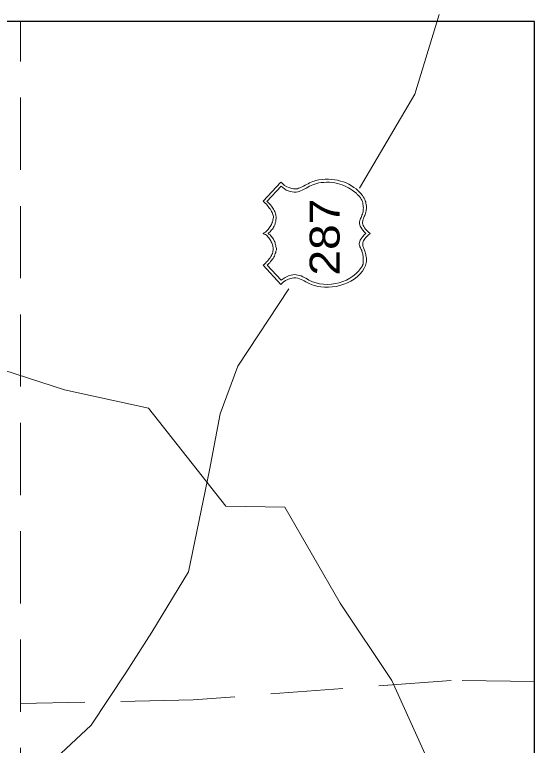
# Model space of a CAD drawing. Extents: x 2363323 to 2367082, y 6956018 to 6980837.
# Drawn here: x 2366145.8 to 2366234.3, y 6956959.3 to 6957083.7 of the extents above; entities that cross this region are included whole.
import ezdxf

# ---------------------------------------------------------------- set-up
doc = ezdxf.new("R2010")
doc.units = 0
doc.header["$LTSCALE"] = 4.1
doc.linetypes.add('MEDIUM_DASHED', pattern=[4.5, 3, -1.5])
doc.layers.add('62', color=7, linetype='Continuous', lineweight=13)
doc.layers.add('63', color=7, linetype='Continuous', lineweight=13)

msp = doc.modelspace()

# ---------------------------------------------------------------- linework, layer by layer
at = {"layer": '62'}
for p, q in [((2366218.108, 6957083.742), (2366213.919, 6957070.216)), ((2366213.919, 6957070.216), (2366204.537, 6957054.172)), ((2366183.835, 6957023.884), (2366192.476, 6957037.071))]:
    msp.add_line(p, q, dxfattribs=at)
at = {"layer": '62', "linetype": 'MEDIUM_DASHED'}
msp.add_line((2366146.841, 6956632.956), (2366146.84, 6957082.55), dxfattribs=at)
at = {"layer": '62', "lineweight": 25}
msp.add_lwpolyline([(2365769.011, 6956632.956), (2366234.284, 6956632.956), (2366234.284, 6957082.548), (2365769.009, 6957082.548)], dxfattribs=at)
at = {"layer": '62'}
for points in [[(2366191.149, 6957037.815), (2366188.156, 6957041.076), (2366188.336, 6957041.258), (2366188.539, 6957041.436), (2366188.696, 6957041.638), (2366188.877, 6957041.796), (2366189.033, 6957042.002), (2366189.17, 6957042.18), (2366189.303, 6957042.36), (2366189.439, 6957042.562), (2366189.53, 6957042.72), (2366189.619, 6957042.922), (2366189.71, 6957043.102), (2366189.755, 6957043.305), (2366189.8, 6957043.485), (2366189.842, 6957043.642), (2366189.845, 6957043.868), (2366189.845, 6957044.07), (2366189.799, 6957044.205), (2366189.753, 6957044.362), (2366189.731, 6957044.542), (2366189.663, 6957044.721), (2366189.596, 6957044.904), (2366189.506, 6957045.06), (2366189.439, 6957045.242), (2366189.35, 6957045.42), (2366189.215, 6957045.578), (2366189.08, 6957045.758), (2366188.945, 6957045.915), (2366188.833, 6957046.072), (2366188.673, 6957046.185), (2366188.517, 6957046.32), (2366188.315, 6957046.388), (2366188.157, 6957046.5), (2366188.313, 6957046.612), (2366188.516, 6957046.725), (2366188.696, 6957046.86), (2366188.833, 6957046.995), (2366188.99, 6957047.154), (2366189.125, 6957047.332), (2366189.236, 6957047.49), (2366189.35, 6957047.67), (2366189.461, 6957047.848), (2366189.573, 6957048.008), (2366189.62, 6957048.232), (2366189.709, 6957048.392), (2366189.755, 6957048.638), (2366189.799, 6957048.795), (2366189.845, 6957049.02), (2366189.867, 6957049.202), (2366189.866, 6957049.358), (2366189.843, 6957049.56), (2366189.777, 6957049.695), (2366189.733, 6957049.896), (2366189.663, 6957050.078), (2366189.573, 6957050.236), (2366189.485, 6957050.394), (2366189.371, 6957050.595), (2366189.236, 6957050.754), (2366189.125, 6957050.932), (2366188.966, 6957051.09), (2366188.831, 6957051.292), (2366188.675, 6957051.452), (2366188.493, 6957051.63), (2366188.313, 6957051.788), (2366188.156, 6957051.968), (2366191.149, 6957055.232), (2366191.465, 6957054.938), (2366191.779, 6957054.646), (2366192.161, 6957054.442), (2366192.566, 6957054.286), (2366192.95, 6957054.128), (2366193.287, 6957054.058), (2366193.579, 6957054.06), (2366193.781, 6957054.06), (2366193.963, 6957054.105), (2366194.163, 6957054.174), (2366194.345, 6957054.24), (2366194.569, 6957054.33), (2366194.793, 6957054.442), (2366195.019, 6957054.555), (2366195.266, 6957054.692), (2366195.513, 6957054.825), (2366195.785, 6957054.96), (2366196.031, 6957055.095), (2366196.325, 6957055.208), (2366196.573, 6957055.32), (2366196.82, 6957055.41), (2366197.066, 6957055.5), (2366197.337, 6957055.568), (2366197.583, 6957055.612), (2366198.147, 6957055.68), (2366198.71, 6957055.749), (2366199.227, 6957055.748), (2366199.766, 6957055.68), (2366200.306, 6957055.636), (2366200.803, 6957055.545), (2366201.297, 6957055.41), (2366201.791, 6957055.252), (2366202.263, 6957055.095), (2366202.737, 6957054.87)], [(2366203.501, 6957053.678), (2366203.277, 6957053.88), (2366202.961, 6957054.062), (2366202.647, 6957054.24), (2366202.309, 6957054.42), (2366201.95, 6957054.578), (2366201.567, 6957054.736), (2366201.185, 6957054.872), (2366200.756, 6957054.982), (2366200.307, 6957055.095), (2366199.879, 6957055.14), (2366199.407, 6957055.206), (2366198.933, 6957055.209), (2366198.44, 6957055.185), (2366198.011, 6957055.14), (2366197.607, 6957055.095), (2366197.27, 6957054.984), (2366196.91, 6957054.892), (2366196.593, 6957054.758), (2366196.301, 6957054.645), (2366196.009, 6957054.51), (2366195.74, 6957054.352), (2366195.469, 6957054.196), (2366195.243, 6957054.06), (2366194.996, 6957053.948), (2366194.749, 6957053.835), (2366194.48, 6957053.722), (2366194.255, 6957053.655), (2366194.006, 6957053.588), (2366193.736, 6957053.542), (2366193.421, 6957053.52), (2366193.083, 6957053.588), (2366192.746, 6957053.655), (2366192.409, 6957053.745), (2366192.05, 6957053.88), (2366191.756, 6957054.06), (2366191.463, 6957054.286), (2366191.171, 6957054.51), (2366188.763, 6957051.945), (2366188.921, 6957051.789), (2366189.08, 6957051.652), (2366189.259, 6957051.495), (2366189.395, 6957051.338), (2366189.551, 6957051.159), (2366189.663, 6957050.978), (2366189.776, 6957050.799), (2366189.889, 6957050.618), (2366190.001, 6957050.415), (2366190.113, 6957050.235), (2366190.181, 6957050.032), (2366190.226, 6957049.854), (2366190.295, 6957049.672), (2366190.316, 6957049.515), (2366190.339, 6957049.359), (2366190.363, 6957049.2), (2366190.339, 6957049.044), (2366190.316, 6957048.862), (2366190.317, 6957048.662), (2366190.271, 6957048.502), (2366190.203, 6957048.278), (2366190.159, 6957048.12), (2366190.091, 6957047.94), (2366190.003, 6957047.738), (2366189.911, 6957047.58), (2366189.821, 6957047.378), (2366189.71, 6957047.244), (2366189.573, 6957047.085), (2366189.461, 6957046.906), (2366189.303, 6957046.772), (2366189.147, 6957046.636), (2366188.966, 6957046.502), (2366189.123, 6957046.365), (2366189.303, 6957046.232), (2366189.416, 6957046.095), (2366189.551, 6957045.96), (2366189.641, 6957045.804), (2366189.753, 6957045.69), (2366189.867, 6957045.51), (2366189.956, 6957045.375), (2366190.025, 6957045.218), (2366190.115, 6957045.038), (2366190.16, 6957044.902), (2366190.203, 6957044.724), (2366190.249, 6957044.565), (2366190.317, 6957044.408), (2366190.316, 6957044.228), (2366190.361, 6957044.072), (2366190.385, 6957043.912), (2366190.383, 6957043.688), (2366190.316, 6957043.485), (2366190.293, 6957043.26), (2366190.203, 6957043.08), (2366190.137, 6957042.854), (2366190.046, 6957042.632), (2366189.933, 6957042.472), (2366189.821, 6957042.248), (2366189.686, 6957042.045), (2366189.573, 6957041.865), (2366189.392, 6957041.706), (2366189.259, 6957041.505), (2366189.079, 6957041.346)], [(2366202.737, 6957054.87), (2366203.163, 6957054.622), (2366203.546, 6957054.33), (2366203.975, 6957054.06), (2366204.333, 6957053.676), (2366204.695, 6957053.34), (2366205.01, 6957052.935), (2366205.167, 6957052.71), (2366205.301, 6957052.509), (2366205.413, 6957052.282), (2366205.503, 6957052.058), (2366205.595, 6957051.855), (2366205.616, 6957051.63), (2366205.663, 6957051.382), (2366205.706, 6957051.182), (2366205.706, 6957050.932), (2366205.706, 6957050.706), (2366205.683, 6957050.505), (2366205.661, 6957050.325), (2366205.593, 6957050.102), (2366205.549, 6957049.92), (2366205.505, 6957049.74), (2366205.413, 6957049.56), (2366205.346, 6957049.382), (2366205.28, 6957049.2), (2366205.211, 6957049.065), (2366205.145, 6957048.885), (2366205.121, 6957048.75), (2366205.076, 6957048.57), (2366205.031, 6957048.392), (2366205.055, 6957048.232), (2366205.1, 6957048.052), (2366205.166, 6957047.85), (2366205.279, 6957047.67), (2366205.391, 6957047.468), (2366205.549, 6957047.242), (2366205.751, 6957047.018), (2366206.021, 6957046.77), (2366206.313, 6957046.5), (2366206.043, 6957046.228), (2366205.819, 6957046.005), (2366205.593, 6957045.802), (2366205.436, 6957045.578), (2366205.303, 6957045.42), (2366205.213, 6957045.24), (2366205.143, 6957045.082), (2366205.1, 6957044.925), (2366205.076, 6957044.79), (2366205.077, 6957044.632), (2366205.077, 6957044.498), (2366205.121, 6957044.342), (2366205.166, 6957044.229), (2366205.189, 6957044.07), (2366205.279, 6957043.914), (2366205.323, 6957043.778), (2366205.391, 6957043.644), (2366205.437, 6957043.485), (2366205.503, 6957043.305), (2366205.549, 6957043.102), (2366205.593, 6957042.922), (2366205.616, 6957042.72), (2366205.663, 6957042.518), (2366205.707, 6957042.339), (2366205.706, 6957042.114), (2366205.706, 6957041.91), (2366205.707, 6957041.706), (2366205.663, 6957041.46), (2366205.617, 6957041.256), (2366205.549, 6957041.031), (2366205.459, 6957040.808), (2366205.346, 6957040.581), (2366205.009, 6957040.064), (2366204.581, 6957039.567), (2366204.131, 6957039.096), (2366203.613, 6957038.714), (2366203.053, 6957038.354), (2366202.466, 6957038.062), (2366201.859, 6957037.838), (2366201.206, 6957037.634), (2366200.555, 6957037.476), (2366199.901, 6957037.386), (2366199.226, 6957037.341), (2366198.573, 6957037.34), (2366197.919, 6957037.408), (2366197.293, 6957037.521), (2366196.661, 6957037.701), (2366196.099, 6957037.926), (2366195.873, 6957038.016), (2366195.626, 6957038.128), (2366195.401, 6957038.264), (2366195.133, 6957038.398), (2366194.863, 6957038.535), (2366194.593, 6957038.668), (2366194.321, 6957038.782), (2366194.03, 6957038.848), (2366193.715, 6957038.916), (2366193.376, 6957038.918), (2366193.04, 6957038.894), (2366192.701, 6957038.804), (2366192.319, 6957038.67), (2366191.937, 6957038.466)], [(2366188.809, 6957041.078), (2366191.171, 6957038.511), (2366191.533, 6957038.781), (2366191.893, 6957039.006), (2366192.229, 6957039.164), (2366192.543, 6957039.321), (2366192.881, 6957039.388), (2366193.173, 6957039.456), (2366193.443, 6957039.478), (2366193.759, 6957039.458), (2366194.053, 6957039.39), (2366194.321, 6957039.344), (2366194.593, 6957039.254), (2366194.863, 6957039.118), (2366195.131, 6957039.008), (2366195.401, 6957038.871), (2366195.65, 6957038.715), (2366195.919, 6957038.556), (2366196.503, 6957038.264), (2366197.135, 6957038.062), (2366197.741, 6957037.904), (2366198.416, 6957037.836), (2366199.069, 6957037.814), (2366199.743, 6957037.836), (2366200.419, 6957037.948), (2366201.049, 6957038.084), (2366201.679, 6957038.286), (2366202.309, 6957038.556), (2366202.873, 6957038.871), (2366203.413, 6957039.21), (2366203.883, 6957039.614), (2366204.333, 6957040.041), (2366204.695, 6957040.514), (2366205.009, 6957040.986), (2366205.053, 6957041.098), (2366205.123, 6957041.234), (2366205.143, 6957041.391), (2366205.143, 6957041.571), (2366205.166, 6957041.706), (2366205.167, 6957041.888), (2366205.167, 6957042.068), (2366205.167, 6957042.248), (2366205.145, 6957042.45), (2366205.143, 6957042.608), (2366205.1, 6957042.808), (2366205.076, 6957042.99), (2366205.033, 6957043.148), (2366204.987, 6957043.328), (2366204.919, 6957043.485), (2366204.896, 6957043.62), (2366204.807, 6957043.755), (2366204.737, 6957043.912), (2366204.673, 6957044.025), (2366204.603, 6957044.181), (2366204.559, 6957044.34), (2366204.537, 6957044.475), (2366204.493, 6957044.632), (2366204.491, 6957044.79), (2366204.536, 6957044.948), (2366204.581, 6957045.152), (2366204.626, 6957045.33), (2366204.761, 6957045.508), (2366204.896, 6957045.736), (2366205.121, 6957045.96), (2366205.346, 6957046.23), (2366205.617, 6957046.478), (2366205.323, 6957046.77), (2366205.076, 6957047.04), (2366204.897, 6957047.286), (2366204.739, 6957047.535), (2366204.626, 6957047.738), (2366204.581, 6957047.94), (2366204.536, 6957048.12), (2366204.536, 6957048.345), (2366204.536, 6957048.504), (2366204.581, 6957048.66), (2366204.626, 6957048.862), (2366204.693, 6957049.042), (2366204.783, 6957049.202), (2366204.849, 6957049.38), (2366204.92, 6957049.582), (2366205.01, 6957049.785), (2366205.077, 6957049.988), (2366205.143, 6957050.188), (2366205.167, 6957050.392), (2366205.166, 6957050.618), (2366205.189, 6957050.822), (2366205.167, 6957051.046), (2366205.166, 6957051.248), (2366205.121, 6957051.471), (2366205.077, 6957051.698), (2366205.009, 6957051.9), (2366204.897, 6957052.126), (2366204.806, 6957052.328), (2366204.671, 6957052.53), (2366204.537, 6957052.755), (2366204.356, 6957052.935), (2366204.153, 6957053.138), (2366203.997, 6957053.318), (2366203.749, 6957053.498), (2366203.501, 6957053.678)], [(2366110.005, 6957040.964), (2366118.917, 6957035.408), (2366135.569, 6957025.954), (2366154.313, 6957019.88), (2366168.645, 6957016.73), (2366181.763, 6957000.033), (2366191.825, 6956999.896), (2366201.229, 6956983.562), (2366210.049, 6956970.398), (2366217.273, 6956954.331), (2366221.505, 6956931.918), (2366225.871, 6956912.838), (2366231.269, 6956892.045), (2366234.285, 6956879.512)], [(2366189.079, 6957041.346), (2366188.945, 6957041.211), (2366188.809, 6957041.078)], [(2366191.937, 6957038.466), (2366191.555, 6957038.196), (2366191.149, 6957037.815)], [(2366183.835, 6957023.884), (2366180.818, 6957015.807), (2366178.975, 6957006.176), (2366175.418, 6956988.872), (2366169.163, 6956978.613), (2366164.755, 6956971.702), (2366158.837, 6956962.79), (2366149.451, 6956953.994), (2366139.257, 6956947.851), (2366127.827, 6956941.91), (2366114.279, 6956933.45), (2366105.707, 6956926.023), (2366097.203, 6956920.33), (2366086.516, 6956914.052), (2366081.631, 6956910.07), (2366068.895, 6956903.004)]]:
    msp.add_lwpolyline(points, dxfattribs=at)
at = {"layer": '62', "linetype": 'MEDIUM_DASHED'}
msp.add_lwpolyline([(2366234.285, 6956970.219), (2366220.109, 6956970.399), (2366176.207, 6956967.09), (2366146.84, 6956966.46)], dxfattribs=at)
at = {"layer": '63'}
for p, q in [((2366218.108, 6957083.742), (2366213.919, 6957070.216)), ((2366213.919, 6957070.216), (2366204.537, 6957054.172)), ((2366183.835, 6957023.884), (2366192.476, 6957037.071))]:
    msp.add_line(p, q, dxfattribs=at)
at = {"layer": '63', "linetype": 'MEDIUM_DASHED'}
msp.add_line((2366146.841, 6956632.956), (2366146.84, 6957082.55), dxfattribs=at)
at = {"layer": '63', "lineweight": 25}
msp.add_lwpolyline([(2365769.011, 6956632.956), (2366234.284, 6956632.956), (2366234.284, 6957082.548), (2365769.009, 6957082.548)], dxfattribs=at)
at = {"layer": '63'}
for points in [[(2366191.149, 6957037.815), (2366188.156, 6957041.076), (2366188.336, 6957041.258), (2366188.539, 6957041.436), (2366188.696, 6957041.638), (2366188.877, 6957041.796), (2366189.033, 6957042.002), (2366189.17, 6957042.18), (2366189.303, 6957042.36), (2366189.439, 6957042.562), (2366189.53, 6957042.72), (2366189.619, 6957042.922), (2366189.71, 6957043.102), (2366189.755, 6957043.305), (2366189.8, 6957043.485), (2366189.842, 6957043.642), (2366189.845, 6957043.868), (2366189.845, 6957044.07), (2366189.799, 6957044.205), (2366189.753, 6957044.362), (2366189.731, 6957044.542), (2366189.663, 6957044.721), (2366189.596, 6957044.904), (2366189.506, 6957045.06), (2366189.439, 6957045.242), (2366189.35, 6957045.42), (2366189.215, 6957045.578), (2366189.08, 6957045.758), (2366188.945, 6957045.915), (2366188.833, 6957046.072), (2366188.673, 6957046.185), (2366188.517, 6957046.32), (2366188.315, 6957046.388), (2366188.157, 6957046.5), (2366188.313, 6957046.612), (2366188.516, 6957046.725), (2366188.696, 6957046.86), (2366188.833, 6957046.995), (2366188.99, 6957047.154), (2366189.125, 6957047.332), (2366189.236, 6957047.49), (2366189.35, 6957047.67), (2366189.461, 6957047.848), (2366189.573, 6957048.008), (2366189.62, 6957048.232), (2366189.709, 6957048.392), (2366189.755, 6957048.638), (2366189.799, 6957048.795), (2366189.845, 6957049.02), (2366189.867, 6957049.202), (2366189.866, 6957049.358), (2366189.843, 6957049.56), (2366189.777, 6957049.695), (2366189.733, 6957049.896), (2366189.663, 6957050.078), (2366189.573, 6957050.236), (2366189.485, 6957050.394), (2366189.371, 6957050.595), (2366189.236, 6957050.754), (2366189.125, 6957050.932), (2366188.966, 6957051.09), (2366188.831, 6957051.292), (2366188.675, 6957051.452), (2366188.493, 6957051.63), (2366188.313, 6957051.788), (2366188.156, 6957051.968), (2366191.149, 6957055.232), (2366191.465, 6957054.938), (2366191.779, 6957054.646), (2366192.161, 6957054.442), (2366192.566, 6957054.286), (2366192.95, 6957054.128), (2366193.287, 6957054.058), (2366193.579, 6957054.06), (2366193.781, 6957054.06), (2366193.963, 6957054.105), (2366194.163, 6957054.174), (2366194.345, 6957054.24), (2366194.569, 6957054.33), (2366194.793, 6957054.442), (2366195.019, 6957054.555), (2366195.266, 6957054.692), (2366195.513, 6957054.825), (2366195.785, 6957054.96), (2366196.031, 6957055.095), (2366196.325, 6957055.208), (2366196.573, 6957055.32), (2366196.82, 6957055.41), (2366197.066, 6957055.5), (2366197.337, 6957055.568), (2366197.583, 6957055.612), (2366198.147, 6957055.68), (2366198.71, 6957055.749), (2366199.227, 6957055.748), (2366199.766, 6957055.68), (2366200.306, 6957055.636), (2366200.803, 6957055.545), (2366201.297, 6957055.41), (2366201.791, 6957055.252), (2366202.263, 6957055.095), (2366202.737, 6957054.87)], [(2366203.501, 6957053.678), (2366203.277, 6957053.88), (2366202.961, 6957054.062), (2366202.647, 6957054.24), (2366202.309, 6957054.42), (2366201.95, 6957054.578), (2366201.567, 6957054.736), (2366201.185, 6957054.872), (2366200.756, 6957054.982), (2366200.307, 6957055.095), (2366199.879, 6957055.14), (2366199.407, 6957055.206), (2366198.933, 6957055.209), (2366198.44, 6957055.185), (2366198.011, 6957055.14), (2366197.607, 6957055.095), (2366197.27, 6957054.984), (2366196.91, 6957054.892), (2366196.593, 6957054.758), (2366196.301, 6957054.645), (2366196.009, 6957054.51), (2366195.74, 6957054.352), (2366195.469, 6957054.196), (2366195.243, 6957054.06), (2366194.996, 6957053.948), (2366194.749, 6957053.835), (2366194.48, 6957053.722), (2366194.255, 6957053.655), (2366194.006, 6957053.588), (2366193.736, 6957053.542), (2366193.421, 6957053.52), (2366193.083, 6957053.588), (2366192.746, 6957053.655), (2366192.409, 6957053.745), (2366192.05, 6957053.88), (2366191.756, 6957054.06), (2366191.463, 6957054.286), (2366191.171, 6957054.51), (2366188.763, 6957051.945), (2366188.921, 6957051.789), (2366189.08, 6957051.652), (2366189.259, 6957051.495), (2366189.395, 6957051.338), (2366189.551, 6957051.159), (2366189.663, 6957050.978), (2366189.776, 6957050.799), (2366189.889, 6957050.618), (2366190.001, 6957050.415), (2366190.113, 6957050.235), (2366190.181, 6957050.032), (2366190.226, 6957049.854), (2366190.295, 6957049.672), (2366190.316, 6957049.515), (2366190.339, 6957049.359), (2366190.363, 6957049.2), (2366190.339, 6957049.044), (2366190.316, 6957048.862), (2366190.317, 6957048.662), (2366190.271, 6957048.502), (2366190.203, 6957048.278), (2366190.159, 6957048.12), (2366190.091, 6957047.94), (2366190.003, 6957047.738), (2366189.911, 6957047.58), (2366189.821, 6957047.378), (2366189.71, 6957047.244), (2366189.573, 6957047.085), (2366189.461, 6957046.906), (2366189.303, 6957046.772), (2366189.147, 6957046.636), (2366188.966, 6957046.502), (2366189.123, 6957046.365), (2366189.303, 6957046.232), (2366189.416, 6957046.095), (2366189.551, 6957045.96), (2366189.641, 6957045.804), (2366189.753, 6957045.69), (2366189.867, 6957045.51), (2366189.956, 6957045.375), (2366190.025, 6957045.218), (2366190.115, 6957045.038), (2366190.16, 6957044.902), (2366190.203, 6957044.724), (2366190.249, 6957044.565), (2366190.317, 6957044.408), (2366190.316, 6957044.228), (2366190.361, 6957044.072), (2366190.385, 6957043.912), (2366190.383, 6957043.688), (2366190.316, 6957043.485), (2366190.293, 6957043.26), (2366190.203, 6957043.08), (2366190.137, 6957042.854), (2366190.046, 6957042.632), (2366189.933, 6957042.472), (2366189.821, 6957042.248), (2366189.686, 6957042.045), (2366189.573, 6957041.865), (2366189.392, 6957041.706), (2366189.259, 6957041.505), (2366189.079, 6957041.346)], [(2366202.737, 6957054.87), (2366203.163, 6957054.622), (2366203.546, 6957054.33), (2366203.975, 6957054.06), (2366204.333, 6957053.676), (2366204.695, 6957053.34), (2366205.01, 6957052.935), (2366205.167, 6957052.71), (2366205.301, 6957052.509), (2366205.413, 6957052.282), (2366205.503, 6957052.058), (2366205.595, 6957051.855), (2366205.616, 6957051.63), (2366205.663, 6957051.382), (2366205.706, 6957051.182), (2366205.706, 6957050.932), (2366205.706, 6957050.706), (2366205.683, 6957050.505), (2366205.661, 6957050.325), (2366205.593, 6957050.102), (2366205.549, 6957049.92), (2366205.505, 6957049.74), (2366205.413, 6957049.56), (2366205.346, 6957049.382), (2366205.28, 6957049.2), (2366205.211, 6957049.065), (2366205.145, 6957048.885), (2366205.121, 6957048.75), (2366205.076, 6957048.57), (2366205.031, 6957048.392), (2366205.055, 6957048.232), (2366205.1, 6957048.052), (2366205.166, 6957047.85), (2366205.279, 6957047.67), (2366205.391, 6957047.468), (2366205.549, 6957047.242), (2366205.751, 6957047.018), (2366206.021, 6957046.77), (2366206.313, 6957046.5), (2366206.043, 6957046.228), (2366205.819, 6957046.005), (2366205.593, 6957045.802), (2366205.436, 6957045.578), (2366205.303, 6957045.42), (2366205.213, 6957045.24), (2366205.143, 6957045.082), (2366205.1, 6957044.925), (2366205.076, 6957044.79), (2366205.077, 6957044.632), (2366205.077, 6957044.498), (2366205.121, 6957044.342), (2366205.166, 6957044.229), (2366205.189, 6957044.07), (2366205.279, 6957043.914), (2366205.323, 6957043.778), (2366205.391, 6957043.644), (2366205.437, 6957043.485), (2366205.503, 6957043.305), (2366205.549, 6957043.102), (2366205.593, 6957042.922), (2366205.616, 6957042.72), (2366205.663, 6957042.518), (2366205.707, 6957042.339), (2366205.706, 6957042.114), (2366205.706, 6957041.91), (2366205.707, 6957041.706), (2366205.663, 6957041.46), (2366205.617, 6957041.256), (2366205.549, 6957041.031), (2366205.459, 6957040.808), (2366205.346, 6957040.581), (2366205.009, 6957040.064), (2366204.581, 6957039.567), (2366204.131, 6957039.096), (2366203.613, 6957038.714), (2366203.053, 6957038.354), (2366202.466, 6957038.062), (2366201.859, 6957037.838), (2366201.206, 6957037.634), (2366200.555, 6957037.476), (2366199.901, 6957037.386), (2366199.226, 6957037.341), (2366198.573, 6957037.34), (2366197.919, 6957037.408), (2366197.293, 6957037.521), (2366196.661, 6957037.701), (2366196.099, 6957037.926), (2366195.873, 6957038.016), (2366195.626, 6957038.128), (2366195.401, 6957038.264), (2366195.133, 6957038.398), (2366194.863, 6957038.535), (2366194.593, 6957038.668), (2366194.321, 6957038.782), (2366194.03, 6957038.848), (2366193.715, 6957038.916), (2366193.376, 6957038.918), (2366193.04, 6957038.894), (2366192.701, 6957038.804), (2366192.319, 6957038.67), (2366191.937, 6957038.466)], [(2366188.809, 6957041.078), (2366191.171, 6957038.511), (2366191.533, 6957038.781), (2366191.893, 6957039.006), (2366192.229, 6957039.164), (2366192.543, 6957039.321), (2366192.881, 6957039.388), (2366193.173, 6957039.456), (2366193.443, 6957039.478), (2366193.759, 6957039.458), (2366194.053, 6957039.39), (2366194.321, 6957039.344), (2366194.593, 6957039.254), (2366194.863, 6957039.118), (2366195.131, 6957039.008), (2366195.401, 6957038.871), (2366195.65, 6957038.715), (2366195.919, 6957038.556), (2366196.503, 6957038.264), (2366197.135, 6957038.062), (2366197.741, 6957037.904), (2366198.416, 6957037.836), (2366199.069, 6957037.814), (2366199.743, 6957037.836), (2366200.419, 6957037.948), (2366201.049, 6957038.084), (2366201.679, 6957038.286), (2366202.309, 6957038.556), (2366202.873, 6957038.871), (2366203.413, 6957039.21), (2366203.883, 6957039.614), (2366204.333, 6957040.041), (2366204.695, 6957040.514), (2366205.009, 6957040.986), (2366205.053, 6957041.098), (2366205.123, 6957041.234), (2366205.143, 6957041.391), (2366205.143, 6957041.571), (2366205.166, 6957041.706), (2366205.167, 6957041.888), (2366205.167, 6957042.068), (2366205.167, 6957042.248), (2366205.145, 6957042.45), (2366205.143, 6957042.608), (2366205.1, 6957042.808), (2366205.076, 6957042.99), (2366205.033, 6957043.148), (2366204.987, 6957043.328), (2366204.919, 6957043.485), (2366204.896, 6957043.62), (2366204.807, 6957043.755), (2366204.737, 6957043.912), (2366204.673, 6957044.025), (2366204.603, 6957044.181), (2366204.559, 6957044.34), (2366204.537, 6957044.475), (2366204.493, 6957044.632), (2366204.491, 6957044.79), (2366204.536, 6957044.948), (2366204.581, 6957045.152), (2366204.626, 6957045.33), (2366204.761, 6957045.508), (2366204.896, 6957045.736), (2366205.121, 6957045.96), (2366205.346, 6957046.23), (2366205.617, 6957046.478), (2366205.323, 6957046.77), (2366205.076, 6957047.04), (2366204.897, 6957047.286), (2366204.739, 6957047.535), (2366204.626, 6957047.738), (2366204.581, 6957047.94), (2366204.536, 6957048.12), (2366204.536, 6957048.345), (2366204.536, 6957048.504), (2366204.581, 6957048.66), (2366204.626, 6957048.862), (2366204.693, 6957049.042), (2366204.783, 6957049.202), (2366204.849, 6957049.38), (2366204.92, 6957049.582), (2366205.01, 6957049.785), (2366205.077, 6957049.988), (2366205.143, 6957050.188), (2366205.167, 6957050.392), (2366205.166, 6957050.618), (2366205.189, 6957050.822), (2366205.167, 6957051.046), (2366205.166, 6957051.248), (2366205.121, 6957051.471), (2366205.077, 6957051.698), (2366205.009, 6957051.9), (2366204.897, 6957052.126), (2366204.806, 6957052.328), (2366204.671, 6957052.53), (2366204.537, 6957052.755), (2366204.356, 6957052.935), (2366204.153, 6957053.138), (2366203.997, 6957053.318), (2366203.749, 6957053.498), (2366203.501, 6957053.678)], [(2366110.005, 6957040.964), (2366118.917, 6957035.408), (2366135.569, 6957025.954), (2366154.313, 6957019.88), (2366168.645, 6957016.73), (2366181.763, 6957000.033), (2366191.825, 6956999.896), (2366201.229, 6956983.562), (2366210.049, 6956970.398), (2366217.273, 6956954.331), (2366221.505, 6956931.918), (2366225.871, 6956912.838), (2366231.269, 6956892.045), (2366234.285, 6956879.512)], [(2366189.079, 6957041.346), (2366188.945, 6957041.211), (2366188.809, 6957041.078)], [(2366191.937, 6957038.466), (2366191.555, 6957038.196), (2366191.149, 6957037.815)], [(2366183.835, 6957023.884), (2366180.818, 6957015.807), (2366178.975, 6957006.176), (2366175.418, 6956988.872), (2366169.163, 6956978.613), (2366164.755, 6956971.702), (2366158.837, 6956962.79), (2366149.451, 6956953.994), (2366139.257, 6956947.851), (2366127.827, 6956941.91), (2366114.279, 6956933.45), (2366105.707, 6956926.023), (2366097.203, 6956920.33), (2366086.516, 6956914.052), (2366081.631, 6956910.07), (2366068.895, 6956903.004)]]:
    msp.add_lwpolyline(points, dxfattribs=at)
at = {"layer": '63', "linetype": 'MEDIUM_DASHED'}
msp.add_lwpolyline([(2366234.285, 6956970.219), (2366220.109, 6956970.399), (2366176.207, 6956967.09), (2366146.84, 6956966.46)], dxfattribs=at)

# ---------------------------------------------------------------- texts
at = {"layer": '62', "width": 1.15}
msp.add_text('287', height=5.099, rotation=90, dxfattribs=at).set_placement((2366201.138, 6957039.322))
at = {"layer": '63', "width": 1.15}
msp.add_text('287', height=5.099, rotation=90, dxfattribs=at).set_placement((2366201.138, 6957039.322))

doc.saveas('drawing.dxf')
